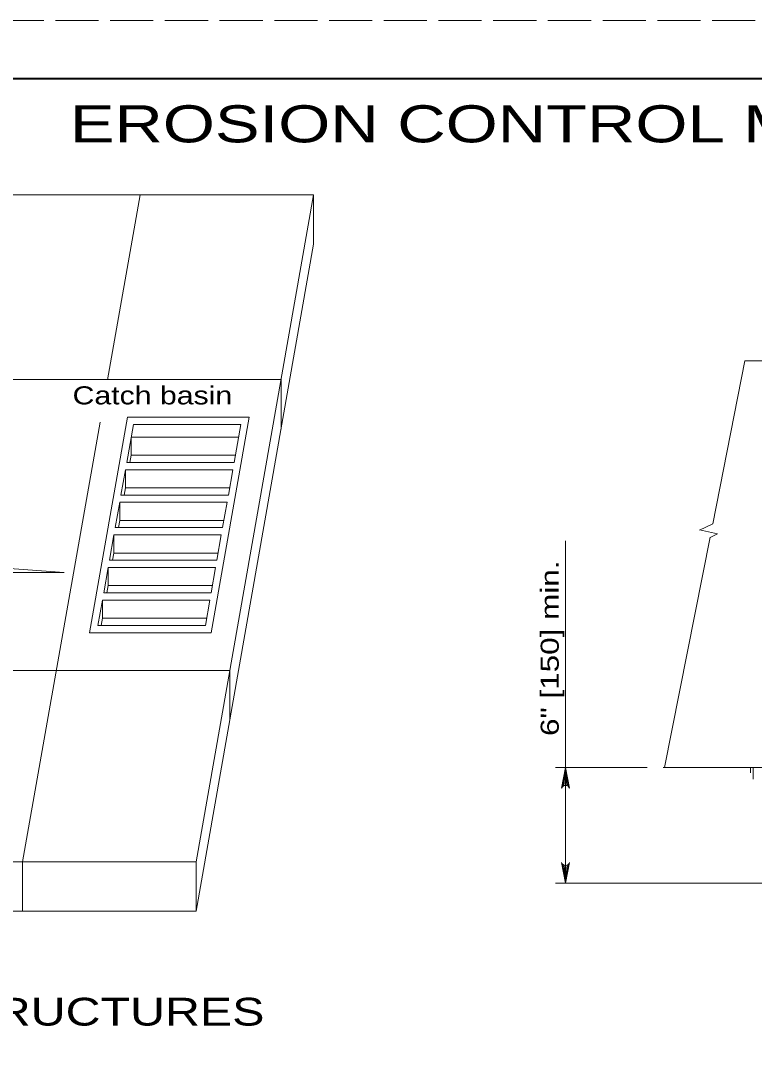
# Model space of a CAD drawing. Extents: x 1083.1 to 1117.1, y 719.4 to 741.4.
# Drawn here: x 1090.49 to 1096.82, y 732.5 to 741.35 of the extents above; entities that cross this region are included whole.
import ezdxf
from ezdxf.enums import TextEntityAlignment as Align

# ---------------------------------------------------------------- set-up
doc = ezdxf.new("R2010")
doc.units = 0
doc.header["$LTSCALE"] = 0.062
doc.linetypes.add('LONG_DASHED', pattern=[7.5, 6, -1.5])
doc.layers.add('1', color=7, linetype='Continuous', lineweight=13)

msp = doc.modelspace()

# ---------------------------------------------------------------- linework, layer by layer
at = {"layer": '1', "lineweight": 25}
msp.add_line((1085.12642, 740.85408), (1116.62642, 740.85408), dxfattribs=at)
at = {"layer": '1'}
for p, q in [((1093.0215, 739.8515), (1089.52617, 739.8515)), ((1091.2425, 738.25408), (1091.52417, 739.8515)), ((1092.00725, 734.09967), (1093.0215, 739.8515)), ((1093.0215, 739.4245), (1093.0215, 739.8515)), ((1093.0215, 739.4245), (1092.00725, 733.67267)), ((1096.7415, 738.418), (1096.46408, 737.01408)), ((1096.7415, 738.418), (1098.1975, 738.418)), ((1092.74075, 738.25933), (1089.24533, 738.25933)), ((1092.74017, 737.82908), (1092.74017, 738.25608)), ((1091.0875, 736.07483), (1091.41517, 737.93258)), ((1091.41517, 737.93258), (1092.46633, 737.93258)), ((1092.46633, 737.93258), (1092.13867, 736.07483)), ((1090.50992, 734.09967), (1091.17858, 737.89158)), ((1091.40892, 737.54267), (1091.46667, 737.87008)), ((1091.46667, 737.87008), (1092.39283, 737.87008)), ((1092.39283, 737.87008), (1092.33508, 737.54267)), ((1091.4475, 737.76133), (1092.37375, 737.76133)), ((1091.4475, 737.76133), (1091.4475, 737.60517)), ((1091.4475, 737.60517), (1091.4365, 737.54267)), ((1091.4475, 737.60517), (1092.34617, 737.60517)), ((1091.40892, 737.54267), (1092.33517, 737.54267)), ((1091.35933, 737.26158), (1091.39792, 737.48025)), ((1091.39792, 737.48025), (1092.32417, 737.48025)), ((1091.39792, 737.48025), (1091.39792, 737.32408)), ((1092.32408, 737.48025), (1092.2855, 737.26158)), ((1091.39792, 737.32408), (1091.38692, 737.26158)), ((1091.39792, 737.32408), (1092.29658, 737.32408)), ((1091.35933, 737.26158), (1092.28558, 737.26158)), ((1091.30983, 736.9805), (1091.34833, 737.19917)), ((1091.34825, 737.19917), (1092.2745, 737.19917)), ((1091.34825, 737.19917), (1091.34825, 737.043)), ((1092.2745, 737.19917), (1092.23592, 736.9805)), ((1091.30975, 736.9805), (1092.23592, 736.9805)), ((1091.34825, 737.043), (1091.33725, 736.9805)), ((1091.34825, 737.043), (1092.247, 737.043)), ((1096.464, 737.014), (1096.35017, 736.95892)), ((1091.26025, 736.69942), (1091.29883, 736.91808)), ((1091.29875, 736.91808), (1092.22492, 736.91808)), ((1091.29875, 736.91808), (1091.29875, 736.76192)), ((1092.22492, 736.91808), (1092.18642, 736.69942)), ((1096.44092, 736.89733), (1096.04825, 734.91067)), ((1095.19408, 734.1735), (1095.19408, 736.86808)), ((1091.26017, 736.69942), (1092.18642, 736.69942)), ((1091.29875, 736.76192), (1091.28775, 736.69942)), ((1091.29875, 736.76192), (1092.1975, 736.76192)), ((1091.21067, 736.41833), (1091.24925, 736.637)), ((1091.24917, 736.637), (1092.17542, 736.637)), ((1091.24917, 736.637), (1091.24917, 736.48083)), ((1092.17542, 736.637), (1092.13683, 736.41833)), ((1091.24917, 736.48083), (1091.23817, 736.41833)), ((1091.24917, 736.48083), (1092.14783, 736.48083)), ((1091.161, 736.13725), (1091.19958, 736.35592)), ((1091.19958, 736.35592), (1092.12583, 736.35592)), ((1091.21058, 736.41833), (1092.13683, 736.41833)), ((1092.12583, 736.35592), (1092.08725, 736.13725)), ((1091.19958, 736.19975), (1092.09825, 736.19975)), ((1092.13867, 736.07483), (1091.0875, 736.07483)), ((1091.161, 736.13725), (1092.08725, 736.13725)), ((1092.29817, 735.74967), (1088.80283, 735.74967)), ((1092.29725, 735.31725), (1092.29725, 735.74425)), ((1095.899, 734.91067), (1095.10817, 734.91067)), ((1095.16933, 734.7485), (1095.19408, 734.91067)), ((1095.17967, 734.75467), (1095.19408, 734.91067)), ((1095.19408, 734.7575), (1095.19408, 734.91067)), ((1095.20542, 734.75583), (1095.19408, 734.91067)), ((1095.2165, 734.75042), (1095.19408, 734.91067)), ((1096.04825, 734.91067), (1096.03567, 734.91067)), ((1096.04825, 734.91067), (1097.50425, 734.91067)), ((1096.78883, 734.86517), (1096.78883, 734.91067)), ((1096.81217, 734.81267), (1096.81217, 734.91067)), ((1095.19408, 734.24017), (1095.19408, 733.931)), ((1092.00725, 734.09967), (1088.51183, 734.09967)), ((1090.50992, 733.67267), (1090.50992, 734.09967)), ((1092.00725, 733.67267), (1092.00725, 734.09967)), ((1095.17167, 734.07525), (1095.19408, 733.915)), ((1095.18275, 734.06983), (1095.19408, 733.915)), ((1095.21892, 734.07717), (1095.19408, 733.915)), ((1095.2085, 734.071), (1095.19408, 733.915)), ((1095.19408, 734.06817), (1095.19408, 733.915)), ((1098.11058, 733.915), (1095.10817, 733.915)), ((1092.00725, 733.67267), (1088.51183, 733.67267))]:
    msp.add_line(p, q, dxfattribs=at)
at = {"layer": '1', "linetype": 'LONG_DASHED'}
msp.add_lwpolyline([(1083.12642, 719.35408), (1117.12642, 719.35408), (1117.12642, 741.35408), (1083.12642, 741.35408)], close=True, dxfattribs=at)
at = {"layer": '1', "lineweight": 40}
msp.add_lwpolyline([(1085.12642, 740.85408), (1116.62642, 740.85408), (1116.62642, 719.85408), (1085.12642, 719.85408)], close=True, dxfattribs=at)
msp.add_lwpolyline([(1085.12642, 740.85408), (1116.62642, 740.85408), (1116.62642, 719.85408), (1085.12642, 719.85408)], close=True, dxfattribs=at)
at = {"layer": '1'}
for points in [[(1096.3495, 736.96058), (1096.50408, 736.92692), (1096.44242, 736.897)], [(1089.13208, 736.59283), (1090.86817, 736.59283), (1090.04475, 736.65542), (1090.216, 736.59542)], [(1091.19958, 736.35592), (1091.19958, 736.19975), (1091.18858, 736.13725)], [(1095.15867, 734.73367), (1095.19408, 734.91067), (1095.2295, 734.73367)], [(1095.2295, 734.092), (1095.19408, 733.915), (1095.15867, 734.092)]]:
    msp.add_lwpolyline(points, dxfattribs=at)
for centre, start, end in [((1095.19413, 734.71934), 22.08782, 157.91395), ((1095.19406, 734.10633), 202.08782, 337.91395)]:
    msp.add_arc(centre, 0.0382, start, end, dxfattribs=at)

# ---------------------------------------------------------------- texts
for s, height, width, p in [('EROSION CONTROL MAT TYPE A-F AND TYPE H-I INSTALLATION', 0.32, 1.35, (1090.918, 740.30317)), ('Catch basin', 0.156, 1.25, (1090.94192, 738.04342)), ('CHECK SLOT AT STRUCTURES', 0.24, 1.3, (1086.31508, 732.68608))]:
    msp.add_text(s, height=height, dxfattribs=dict(at, width=width)).set_placement(p)
at = {"layer": '1', "width": 1.3}
msp.add_text('6" [150] min.', height=0.156, rotation=90, dxfattribs=at).set_placement((1095.13567, 735.94071), align=Align.CENTER)

doc.saveas('drawing.dxf')
